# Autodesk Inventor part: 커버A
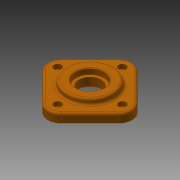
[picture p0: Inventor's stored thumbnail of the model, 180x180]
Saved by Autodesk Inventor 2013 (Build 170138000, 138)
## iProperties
Created: 2013-01
Part Number: 커버A
Document SubType Name: Modeling
Density: 1 g/cm^3
Material: 알루미늄 6061
Designer: mdu
Author: mdu
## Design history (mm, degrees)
sketch "스케치1"
  geometry: L1 (56.569, -14.142)-(14.142, -56.569) reference; L2 (-14.142, -56.569)-(-56.569, -14.142) reference; L3 (-56.569, 14.142)-(-14.142, 56.569) reference; L4 (14.142, 56.569)-(56.569, 14.142) reference; C1 r 31 at (0, 0) reference; A1 r 20 centre (0, -42.426) between (-14.142, -56.569) and (14.142, -56.569) reference; A2 r 20 centre (-42.426, 0) between (-56.569, 14.142) and (-56.569, -14.142) reference; A3 r 20 centre (0, 42.426) between (14.142, 56.569) and (-14.142, 56.569) reference; A4 r 20 centre (42.426, 0) between (56.569, -14.142) and (56.569, 14.142) reference; 1 further point
extrude "돌출1" new body sketch "스케치1" distance "d0" = 13; taper "d1" = 0 deg
sketch "스케치2"
  geometry: C1 r 35 at (0, 0); 1 further point
  constraints: 1 centre point, 1 coincident
  dimensions: "d2" = 70 diameter of C1
extrude "돌출2" join sketch "스케치2" distance "d3" = 8; taper "d4" = 0 deg
fillet "모깎기1" dims "d5" = 3
sketch "스케치3"
  geometry: C1 r 2.458 at (0, 48) reference; 1 further point
hole "구멍1" sketch "스케치3" at (0, 48) diameter "d6" = 6.6; stored, may be unused: countersink angle "d10" = 90 deg, drill point angle "d12" = 118 deg; dims "d7" = 6, "d8" = 11, "d9" = 6.5, "d11" = 8
hole "구멍2" diameter "d18" = 33; stored, may be unused: countersink angle "d22" = 90 deg, drill point angle "d24" = 118 deg; dims "d16" = 10, "d17" = 10, "d19" = 6, "d20" = 42, "d21" = 8.5, "d23" = 8
sketch "스케치4"
  geometry: C1 r 31 at (0, 0) reference; 1 further point
extrude "돌출3" join sketch "스케치4" distance "d25" = 6; taper "d26" = 0 deg
hole "구멍3" diameter "d29" = 50; stored, may be unused: countersink angle "d33" = 90 deg, drill point angle "d35" = 0 deg; dims "d27" = 10, "d28" = 10, "d30" = 6, "d31" = 42, "d32" = 8.5, "d34" = 7
fillet "모깎기2" dims "d36" = 3, "d37" = 0.4
chamfer "모따기1" distance "d38" = 1; stored, may be unused: second distance "d39" = 2, angle "d40" = 45 deg
node "솔리드1"
pattern_circular "원형 패턴1" dims angle "d14" = 360 deg
node "참조1"
node "참조2"
node "참조3"
node "참조4"
node "참조5"
node "참조6"
node "참조7"
node "참조8"
node "참조9"
node "참조10"
node "참조11"
